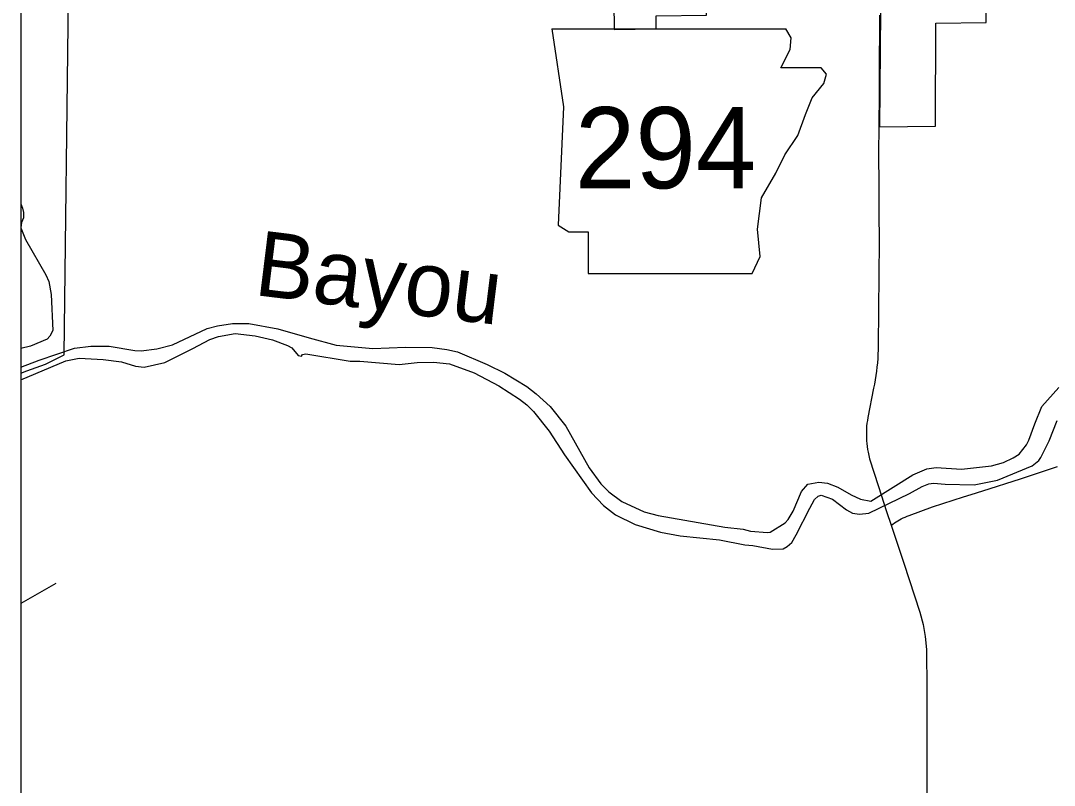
# Model space of a CAD drawing. Extents: x 1127717 to 1741049, y 2026793 to 2244711.
# Drawn here: x 1278363 to 1285080, y 2101518 to 2106486 of the extents above; entities that cross this region are included whole.
import ezdxf

# ---------------------------------------------------------------- set-up
doc = ezdxf.new("R2010")
doc.units = 0
for name, color, linetype in [('1', 7, 'Continuous'), ('21', 7, 'Continuous'), ('31', 7, 'Continuous'), ('35', 7, 'Continuous'), ('43', 7, 'Continuous'), ('45', 7, 'Continuous'), ('6', 7, 'Continuous')]:
    doc.layers.add(name, color=color, linetype=linetype)

msp = doc.modelspace()

# ---------------------------------------------------------------- linework, layer by layer
at = {"layer": '1'}
msp.add_lwpolyline([(1349634.2, 2111942.3), (1278362.7, 2111942.3), (1278362.7, 2066677.1), (1349634.2, 2066677.1)], close=True, dxfattribs=at)
at = {"layer": '21'}
for p, q in [((1281814.5, 2106433.5), (1281890.6, 2105926)), ((1283370.9, 2106374.3), (1283335.9, 2106432.8)), ((1283362.5, 2106298.2), (1283370.9, 2106374.3)), ((1283303.3, 2106179.8), (1283362.5, 2106298.2)), ((1283565.5, 2106179.8), (1283303.3, 2106179.8)), ((1283599.3, 2106137.5), (1283565.5, 2106179.8)), ((1283582.4, 2106078.3), (1283599.3, 2106137.5)), ((1283506.3, 2105985.2), (1283582.4, 2106078.3)), ((1283464, 2105875.2), (1283506.3, 2105985.2)), ((1281890.6, 2105926), (1281856.8, 2105156.2)), ((1283413.2, 2105739.9), (1283464, 2105875.2)), ((1283328.6, 2105613), (1283413.2, 2105739.9)), ((1283269.4, 2105494.6), (1283328.6, 2105613)), ((1283176.4, 2105333.9), (1283269.4, 2105494.6)), ((1283151, 2105130.9), (1283176.4, 2105333.9)), ((1281856.8, 2105156.2), (1281924.5, 2105113.9)), ((1283167.9, 2104953.2), (1283151, 2105130.9)), ((1281924.5, 2105113.9), (1282051.3, 2105113.9)), ((1282051.3, 2105113.9), (1282051.3, 2104843.2)), ((1283117.2, 2104843.2), (1283167.9, 2104953.2)), ((1282051.3, 2104843.2), (1283117.2, 2104843.2))]:
    msp.add_line(p, q, dxfattribs=at)
msp.add_lwpolyline([(1281814.5, 2106433.5), (1283335.9, 2106432.8)], dxfattribs=at)
at = {"layer": '31'}
for points in [[(1283944.2, 2106520.7), (1283943.3, 2106442.5), (1283942.5, 2106203.2), (1283941.6, 2105996.3), (1283939.1, 2105812.9), (1283938.4, 2105610.3), (1283939.9, 2105425.1), (1283940.3, 2105372.7), (1283939.4, 2105243.9), (1283941.1, 2105046), (1283939, 2104835.3), (1283935.2, 2104374.3), (1283934.7, 2104346.4), (1283933.8, 2104318.6), (1283932.4, 2104290.8), (1283930.2, 2104263), (1283927.6, 2104235.2), (1283924.4, 2104207.6), (1283920.6, 2104180), (1283916.2, 2104152.5), (1283911.2, 2104125), (1283905.7, 2104097.7), (1283868.3, 2103907.7), (1283865.3, 2103889), (1283862.7, 2103870.3), (1283860.6, 2103851.4), (1283859.3, 2103832.6), (1283858.5, 2103813.6), (1283858.5, 2103794.7), (1283858.9, 2103775.7), (1283860, 2103756.8), (1283861.5, 2103738), (1283863.9, 2103719.1), (1283866.7, 2103700.4), (1283870.1, 2103681.8), (1283879.4, 2103639.4), (1283936.6, 2103458.2), (1283990.1, 2103296.2), (1284019.3, 2103208)], [(1284019.3, 2103208), (1284101.5, 2102962.1), (1284206.1, 2102642.8), (1284227.3, 2102561.8), (1284241.2, 2102484.5), (1284250.5, 2102400.9), (1284252, 2102141), (1284251.5, 2101414.3)]]:
    msp.add_lwpolyline(points, dxfattribs=at)
at = {"layer": '35'}
for points in [[(1278362.7, 2105295.3), (1278373.6, 2105267.3), (1278380.1, 2105239.3), (1278380.7, 2105205.2), (1278367.2, 2105174.9), (1278363.8, 2105138.7), (1278393.1, 2105063), (1278525.2, 2104834.5), (1278545.9, 2104790.7), (1278561.4, 2104706.7), (1278571.3, 2104472.1), (1278551.9, 2104435.7), (1278534.2, 2104417.4), (1278426.8, 2104371.4), (1278362.7, 2104354.8)], [(1278362.7, 2104233.9), (1278482.4, 2104280.1), (1278713.5, 2104358.2), (1278819.5, 2104369.9), (1278937.7, 2104369.9), (1279104.4, 2104342.6), (1279146.5, 2104341.3), (1279248.4, 2104353), (1279350.2, 2104378.8), (1279574.7, 2104484.8), (1279642.5, 2104504), (1279738.5, 2104517.6), (1279844.6, 2104517.4), (1280033.5, 2104484.4), (1280236.8, 2104425.6), (1280413.9, 2104378.4), (1280650.6, 2104356.3), (1280862.8, 2104363.8), (1281037.1, 2104362.7), (1281131.5, 2104350.2), (1281201.9, 2104333.3), (1281393.6, 2104252.3), (1281508.7, 2104196), (1281652.4, 2104108.1), (1281713.3, 2104061), (1281802.8, 2103978.2), (1281905.1, 2103851.5), (1282057.9, 2103581.2), (1282133.8, 2103476.2), (1282184.8, 2103424.9), (1282270, 2103362.1), (1282415.3, 2103294.3), (1282505.9, 2103269.7), (1282939.8, 2103194.7)], [(1278362.7, 2104153.1), (1278656.8, 2104275), (1278742.6, 2104292.4), (1278899, 2104285), (1279017.5, 2104268.9), (1279108.1, 2104240.3), (1279164.3, 2104235.3), (1279300, 2104265.6), (1279480.8, 2104354.9), (1279591.9, 2104414.9), (1279647.7, 2104433.9), (1279755.6, 2104453.7), (1279886, 2104437.8), (1279998.7, 2104411.6), (1280097.4, 2104375.1), (1280125.7, 2104359.6), (1280166.6, 2104310.1), (1280186.7, 2104306.4), (1280194.6, 2104316.6), (1280216.5, 2104321), (1280503.8, 2104273.6), (1280565.9, 2104272.6), (1280822.6, 2104252.8), (1280938.6, 2104264.8), (1281044.8, 2104266.5), (1281149.1, 2104256.2), (1281310.4, 2104196.7), (1281470, 2104113.1), (1281603.7, 2104027.1), (1281652.4, 2103989.8), (1281695.2, 2103946.3), (1281797.5, 2103819.6), (1281896.3, 2103664.8), (1282072.7, 2103417), (1282150.2, 2103336), (1282227.4, 2103275.1), (1282356.6, 2103213.1), (1282521.7, 2103161.6)], [(1282939.8, 2103194.7), (1283058.2, 2103182.6), (1283106.5, 2103169.4), (1283216.9, 2103159.2), (1283232.8, 2103163.4), (1283330, 2103223.2), (1283349.6, 2103245.6), (1283382.8, 2103298.3), (1283436.7, 2103427.6), (1283478, 2103474.4), (1283549.9, 2103487.7), (1283606.1, 2103480.6), (1283672.6, 2103455.6), (1283759.6, 2103404.9), (1283820.2, 2103375.8), (1283888.5, 2103364.9), (1284160.1, 2103533.9), (1284251.6, 2103573.6), (1284311.5, 2103582.6), (1284476, 2103571.3), (1284671.9, 2103592.6), (1284749.7, 2103614), (1284813.3, 2103645.1), (1284850.9, 2103669.8), (1284900, 2103728.8), (1284915.5, 2103761.1), (1284953.8, 2103866.1), (1284999.9, 2103979.2), (1285110.1, 2104101.4)], [(1282521.7, 2103161.6), (1282648.3, 2103137.7), (1282903.2, 2103111.8), (1283068, 2103080.4), (1283120.1, 2103075.3), (1283248.8, 2103051.4), (1283318.8, 2103054.5), (1283344.6, 2103069), (1283374.2, 2103095.6), (1283403.4, 2103144.2), (1283490.7, 2103318.2), (1283521.7, 2103374.9), (1283545.4, 2103395.3), (1283565.3, 2103403.7), (1283637.9, 2103376.8), (1283729.2, 2103308.1), (1283767.6, 2103286.7), (1283813.8, 2103279.4), (1283873.8, 2103286.4), (1284138.1, 2103413.2), (1284221.5, 2103458.7), (1284265.2, 2103477.5), (1284295.2, 2103480), (1284371.5, 2103473.3), (1284559.8, 2103470.4), (1284711.5, 2103501), (1284936.3, 2103593), (1284979.8, 2103627.8), (1284991.5, 2103648.1), (1285045.8, 2103755.3), (1285099.6, 2103888.6)]]:
    msp.add_lwpolyline(points, dxfattribs=at)
at = {"layer": '43'}
msp.add_lwpolyline([(1278592.2, 2102828), (1278362.7, 2102699.2)], dxfattribs=at)
at = {"layer": '45'}
msp.add_lwpolyline([(1284019.3, 2103208), (1284030, 2103215.3), (1284040.9, 2103222.4), (1284051.8, 2103229.3), (1284062.8, 2103236), (1284073.9, 2103242.5), (1284085.1, 2103248.7), (1284097.7, 2103254.7), (1284110.3, 2103260.5), (1284123, 2103266), (1284135.9, 2103271.2), (1284289.3, 2103326.9), (1284489.7, 2103393), (1284538.9, 2103407.9), (1284615.3, 2103431.1), (1284860.5, 2103507.9), (1285100.2, 2103588.8)], dxfattribs=at)
at = {"layer": '6'}
msp.add_line((1278644.7, 2104314.4), (1278675.5, 2106735.8), dxfattribs=at)
for points in [[(1283951.9, 2106800.4), (1283943.1, 2105796), (1284308.2, 2105800.5), (1284310.3, 2106470), (1284636.8, 2106474.1), (1284637.9, 2106807.6)], [(1278675.5, 2106735.8), (1282214.8, 2106779.2), (1282219, 2106429.2), (1282492.8, 2106432.5), (1282491.8, 2106517.5), (1282820.5, 2106521.5), (1282817.3, 2106786.4), (1283951.9, 2106800.4)], [(1278362.7, 2104195), (1278402.3, 2104210.7), (1278524.2, 2104253.3), (1278644.7, 2104314.4)]]:
    msp.add_lwpolyline(points, dxfattribs=at)

# ---------------------------------------------------------------- texts
at = {"layer": '21'}
msp.add_text('294', height=528, dxfattribs=at).set_placement((1281964.8, 2105396.3))
at = {"layer": '35'}
msp.add_text('Bayou', height=422.4, rotation=352.97734, dxfattribs=at).set_placement((1279872.5, 2104704.3))

doc.saveas('drawing.dxf')
